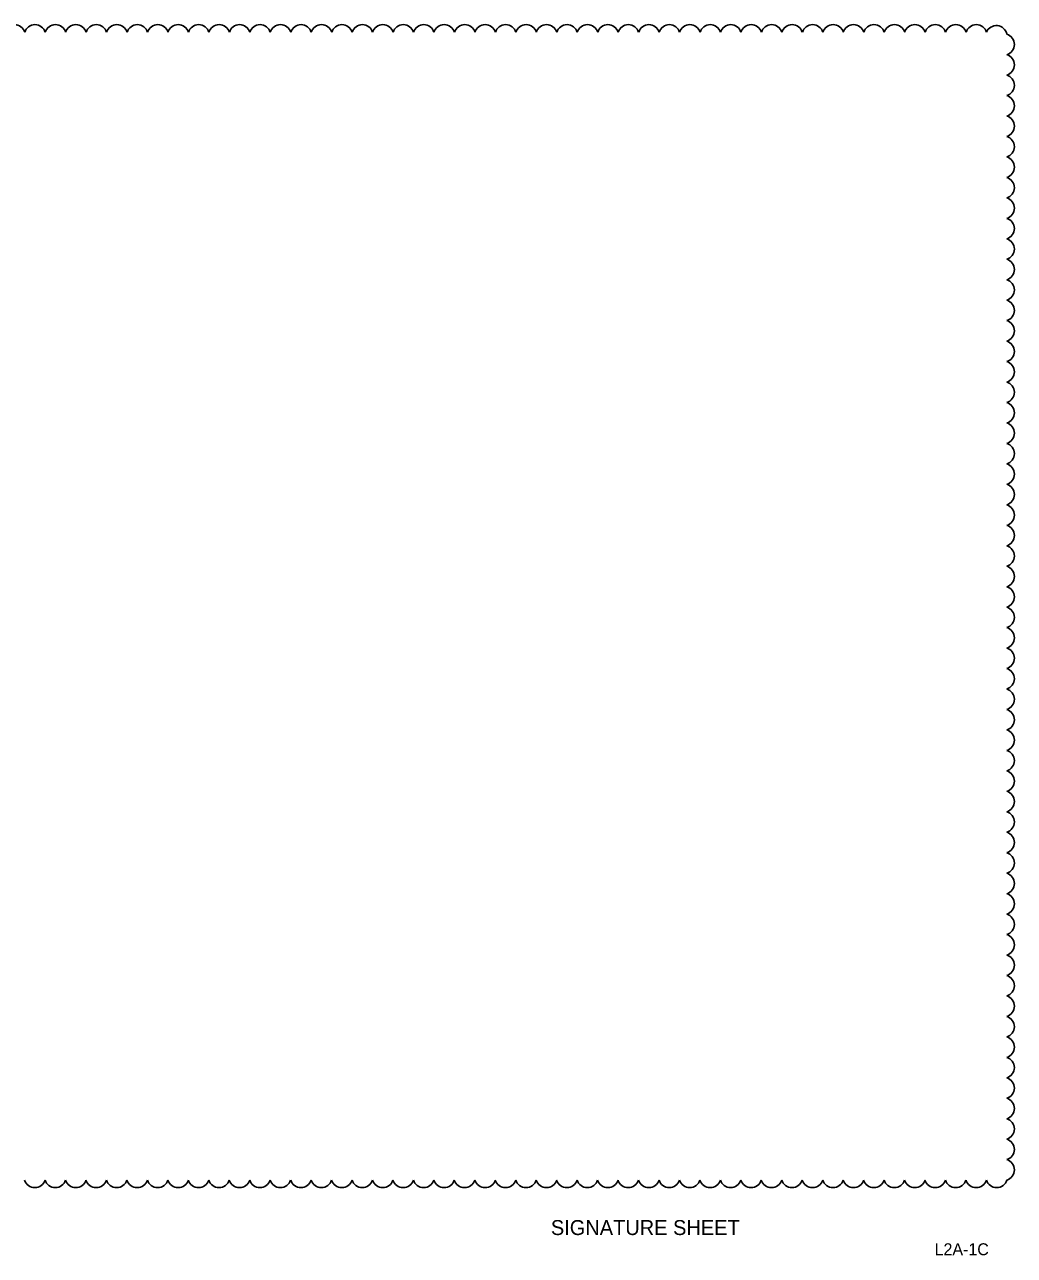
# Model space of a CAD drawing. Extents: x -811 to -790, y -2284 to -2178.
# Drawn here: x -803.6 to -795.32, y -2229.91 to -2219.62 of the extents above; entities that cross this region are included whole.
import ezdxf

# ---------------------------------------------------------------- set-up
doc = ezdxf.new("R2010")
doc.units = 0
for name, color, linetype in [('PlotBorder_dp', 7, 'Continuous'), ('SheetLines_dp', 7, 'Continuous'), ('TextTitle', 7, 'Continuous')]:
    doc.layers.add(name, color=color, linetype=linetype)

msp = doc.modelspace()

# ---------------------------------------------------------------- linework, layer by layer
at = {"layer": 'TextTitle'}
for centre, radius, start, end in [((-803.684, -2219.707), 0.0897, 17.5, 162.5), ((-803.513, -2219.707), 0.0897, 17.5, 162.5), ((-803.342, -2219.707), 0.0897, 17.5, 162.5), ((-803.171, -2219.707), 0.0897, 17.5, 162.5), ((-803, -2219.707), 0.0897, 17.5, 162.5), ((-802.829, -2219.707), 0.0897, 17.5, 162.5), ((-802.657, -2219.707), 0.0897, 17.5, 162.5), ((-802.486, -2219.707), 0.0897, 17.5, 162.5), ((-802.315, -2219.707), 0.0897, 17.5, 162.5), ((-802.144, -2219.707), 0.0897, 17.5, 162.5), ((-801.973, -2219.707), 0.0897, 17.5, 162.5), ((-801.802, -2219.707), 0.0897, 17.5, 162.5), ((-801.631, -2219.707), 0.0897, 17.5, 162.5), ((-801.46, -2219.707), 0.0897, 17.5, 162.5), ((-801.288, -2219.707), 0.0897, 17.5, 162.5), ((-801.117, -2219.707), 0.0897, 17.5, 162.5), ((-800.946, -2219.707), 0.0897, 17.5, 162.5), ((-800.775, -2219.707), 0.0897, 17.5, 162.5), ((-800.604, -2219.707), 0.0897, 17.5, 162.5), ((-800.433, -2219.707), 0.0897, 17.5, 162.5), ((-800.262, -2219.707), 0.0897, 17.5, 162.5), ((-800.091, -2219.707), 0.0897, 17.5, 162.5), ((-799.919, -2219.707), 0.0897, 17.5, 162.5), ((-799.748, -2219.707), 0.0897, 17.5, 162.5), ((-799.577, -2219.707), 0.0897, 17.5, 162.5), ((-799.406, -2219.707), 0.0897, 17.5, 162.5), ((-799.235, -2219.707), 0.0897, 17.5, 162.5), ((-799.064, -2219.707), 0.0897, 17.5, 162.5), ((-798.893, -2219.707), 0.0897, 17.5, 162.5), ((-798.722, -2219.707), 0.0897, 17.5, 162.5), ((-798.551, -2219.707), 0.0897, 17.5, 162.5), ((-798.379, -2219.707), 0.0897, 17.5, 162.5), ((-798.208, -2219.707), 0.0897, 17.5, 162.5), ((-798.037, -2219.707), 0.0897, 17.5, 162.5), ((-797.866, -2219.707), 0.0897, 17.5, 162.5), ((-797.695, -2219.707), 0.0897, 17.5, 162.5), ((-797.524, -2219.707), 0.0897, 17.5, 162.5), ((-797.353, -2219.707), 0.0897, 17.5, 162.5), ((-797.182, -2219.707), 0.0897, 17.5, 162.5), ((-797.01, -2219.707), 0.0897, 17.5, 162.5), ((-796.839, -2219.707), 0.0897, 17.5, 162.5), ((-796.668, -2219.707), 0.0897, 17.5, 162.5), ((-796.497, -2219.707), 0.0897, 17.5, 162.5), ((-796.326, -2219.707), 0.0897, 17.5, 162.5), ((-796.155, -2219.707), 0.0897, 17.5, 162.5), ((-795.984, -2219.707), 0.0897, 17.5, 162.5), ((-795.813, -2219.707), 0.0897, 17.5, 162.5), ((-795.641, -2219.707), 0.0897, 17.5, 162.5), ((-795.474, -2219.715), 0.0896, 11.7454, 156.7454), ((-795.413, -2219.783), 0.0897, 287.5, 72.5), ((-795.413, -2219.954), 0.0897, 287.5, 72.5), ((-795.413, -2220.125), 0.0897, 287.5, 72.5), ((-795.413, -2220.296), 0.0897, 287.5, 72.5), ((-795.413, -2220.467), 0.0897, 287.5, 72.5), ((-795.413, -2220.638), 0.0897, 287.5, 72.5), ((-795.413, -2220.809), 0.0897, 287.5, 72.5), ((-795.413, -2220.981), 0.0897, 287.5, 72.5), ((-795.413, -2221.152), 0.0897, 287.5, 72.5), ((-795.413, -2221.323), 0.0897, 287.5, 72.5), ((-795.413, -2221.494), 0.0897, 287.5, 72.5), ((-795.413, -2221.665), 0.0897, 287.5, 72.5), ((-795.413, -2221.836), 0.0897, 287.5, 72.5), ((-795.413, -2222.007), 0.0897, 287.5, 72.5), ((-795.413, -2222.178), 0.0897, 287.5, 72.5), ((-795.413, -2222.35), 0.0897, 287.5, 72.5), ((-795.413, -2222.521), 0.0897, 287.5, 72.5), ((-795.413, -2222.692), 0.0897, 287.5, 72.5), ((-795.413, -2222.863), 0.0897, 287.5, 72.5), ((-795.413, -2223.034), 0.0897, 287.5, 72.5), ((-795.413, -2223.205), 0.0897, 287.5, 72.5), ((-795.413, -2223.376), 0.0897, 287.5, 72.5), ((-795.413, -2223.547), 0.0897, 287.5, 72.5), ((-795.413, -2223.719), 0.0897, 287.5, 72.5), ((-795.413, -2223.89), 0.0897, 287.5, 72.5), ((-795.413, -2224.061), 0.0897, 287.5, 72.5), ((-795.413, -2224.232), 0.0897, 287.5, 72.5), ((-795.413, -2224.403), 0.0897, 287.5, 72.5), ((-795.413, -2224.574), 0.0897, 287.5, 72.5), ((-795.413, -2224.745), 0.0897, 287.5, 72.5), ((-795.413, -2224.916), 0.0897, 287.5, 72.5), ((-795.413, -2225.087), 0.0897, 287.5, 72.5), ((-795.413, -2225.259), 0.0897, 287.5, 72.5), ((-795.413, -2225.43), 0.0897, 287.5, 72.5), ((-795.413, -2225.601), 0.0897, 287.5, 72.5), ((-795.413, -2225.772), 0.0897, 287.5, 72.5), ((-795.413, -2225.943), 0.0897, 287.5, 72.5), ((-795.413, -2226.114), 0.0897, 287.5, 72.5), ((-795.413, -2226.285), 0.0897, 287.5, 72.5), ((-795.413, -2226.456), 0.0897, 287.5, 72.5), ((-795.413, -2226.628), 0.0897, 287.5, 72.5), ((-795.413, -2226.799), 0.0897, 287.5, 72.5), ((-795.413, -2226.97), 0.0897, 287.5, 72.5), ((-795.413, -2227.141), 0.0897, 287.5, 72.5), ((-795.413, -2227.312), 0.0897, 287.5, 72.5), ((-795.413, -2227.483), 0.0897, 287.5, 72.5), ((-795.413, -2227.654), 0.0897, 287.5, 72.5), ((-795.413, -2227.825), 0.0897, 287.5, 72.5), ((-795.413, -2227.997), 0.0897, 287.5, 72.5), ((-795.413, -2228.168), 0.0897, 287.5, 72.5), ((-795.413, -2228.339), 0.0897, 287.5, 72.5), ((-795.413, -2228.51), 0.0897, 287.5, 72.5), ((-795.413, -2228.681), 0.0897, 287.5, 72.5), ((-795.413, -2228.852), 0.0897, 287.5, 72.5), ((-795.413, -2229.023), 0.0897, 287.5, 72.5), ((-795.413, -2229.194), 0.0897, 287.5, 72.5), ((-803.514, -2229.253), 0.0897, 197.5, 342.5), ((-803.343, -2229.253), 0.0897, 197.5, 342.5), ((-803.172, -2229.253), 0.0897, 197.5, 342.5), ((-803.001, -2229.253), 0.0897, 197.5, 342.5), ((-802.83, -2229.253), 0.0897, 197.5, 342.5), ((-802.658, -2229.253), 0.0897, 197.5, 342.5), ((-802.487, -2229.253), 0.0897, 197.5, 342.5), ((-802.316, -2229.253), 0.0897, 197.5, 342.5), ((-802.145, -2229.253), 0.0897, 197.5, 342.5), ((-801.974, -2229.253), 0.0897, 197.5, 342.5), ((-801.803, -2229.253), 0.0897, 197.5, 342.5), ((-801.632, -2229.253), 0.0897, 197.5, 342.5), ((-801.461, -2229.253), 0.0897, 197.5, 342.5), ((-801.289, -2229.253), 0.0897, 197.5, 342.5), ((-801.118, -2229.253), 0.0897, 197.5, 342.5), ((-800.947, -2229.253), 0.0897, 197.5, 342.5), ((-800.776, -2229.253), 0.0897, 197.5, 342.5), ((-800.605, -2229.253), 0.0897, 197.5, 342.5), ((-800.434, -2229.253), 0.0897, 197.5, 342.5), ((-800.263, -2229.253), 0.0897, 197.5, 342.5), ((-800.092, -2229.253), 0.0897, 197.5, 342.5), ((-799.921, -2229.253), 0.0897, 197.5, 342.5), ((-799.749, -2229.253), 0.0897, 197.5, 342.5), ((-799.578, -2229.253), 0.0897, 197.5, 342.5), ((-799.407, -2229.253), 0.0897, 197.5, 342.5), ((-799.236, -2229.253), 0.0897, 197.5, 342.5), ((-799.065, -2229.253), 0.0897, 197.5, 342.5), ((-798.894, -2229.253), 0.0897, 197.5, 342.5), ((-798.723, -2229.253), 0.0897, 197.5, 342.5), ((-798.552, -2229.253), 0.0897, 197.5, 342.5), ((-798.38, -2229.253), 0.0897, 197.5, 342.5), ((-798.209, -2229.253), 0.0897, 197.5, 342.5), ((-798.038, -2229.253), 0.0897, 197.5, 342.5), ((-797.867, -2229.253), 0.0897, 197.5, 342.5), ((-797.696, -2229.253), 0.0897, 197.5, 342.5), ((-797.525, -2229.253), 0.0897, 197.5, 342.5), ((-797.354, -2229.253), 0.0897, 197.5, 342.5), ((-797.183, -2229.253), 0.0897, 197.5, 342.5), ((-797.011, -2229.253), 0.0897, 197.5, 342.5), ((-796.84, -2229.253), 0.0897, 197.5, 342.5), ((-796.669, -2229.253), 0.0897, 197.5, 342.5), ((-796.498, -2229.253), 0.0897, 197.5, 342.5), ((-796.327, -2229.253), 0.0897, 197.5, 342.5), ((-796.156, -2229.253), 0.0897, 197.5, 342.5), ((-795.985, -2229.253), 0.0897, 197.5, 342.5), ((-795.814, -2229.253), 0.0897, 197.5, 342.5), ((-795.642, -2229.253), 0.0897, 197.5, 342.5), ((-795.471, -2229.253), 0.0897, 197.5, 342.5)]:
    msp.add_arc(centre, radius, start, end, dxfattribs=at)

# ---------------------------------------------------------------- texts
at = {"layer": 'PlotBorder_dp'}
msp.add_text('       SIGNATURE SHEET         ', height=0.125, dxfattribs=at).set_placement((-799.524, -2229.739))
at = {"layer": 'SheetLines_dp'}
msp.add_text('L2A-1C', height=0.1, dxfattribs=at).set_placement((-795.99, -2229.908))

doc.saveas('drawing.dxf')
